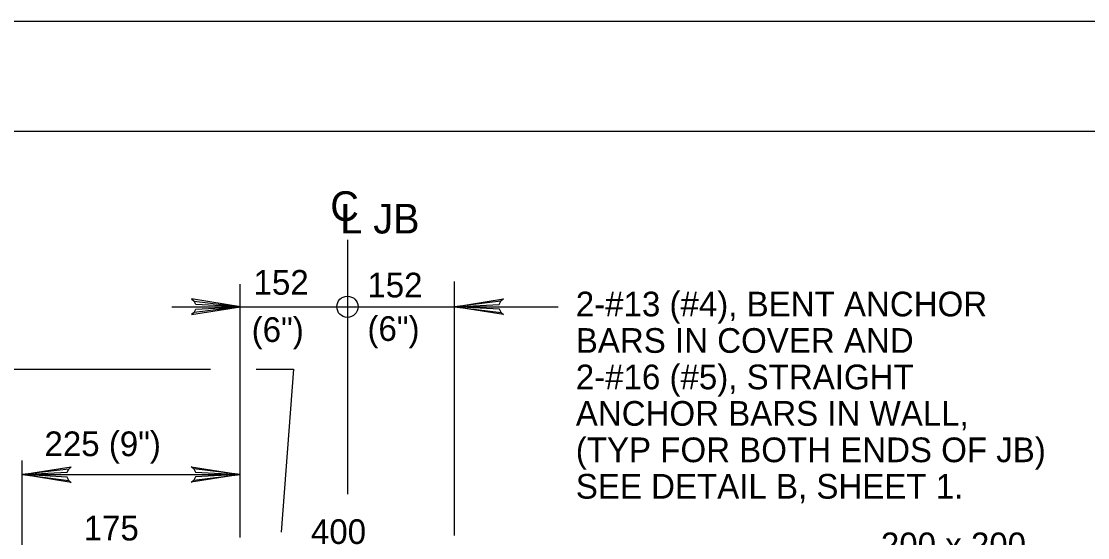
# Model space of a CAD drawing. Extents: x 638455 to 640199, y 298558 to 299152.
# Drawn here: x 639455 to 639600, y 299082 to 299152.2 of the extents above; entities that cross this region are included whole.
import ezdxf

# ---------------------------------------------------------------- set-up
doc = ezdxf.new("R2010")
doc.units = 0
for name, color, linetype in [('1', 7, 'Continuous'), ('2', 7, 'Continuous'), ('3', 7, 'Continuous'), ('PLT-BNDY', 7, 'Continuous')]:
    doc.layers.add(name, color=color, linetype=linetype)

msp = doc.modelspace()

# ---------------------------------------------------------------- linework, layer by layer
at = {"layer": '1'}
msp.add_lwpolyline([(640119.61, 298573.25), (640119.61, 299137.25), (639333.61, 299137.25), (639333.61, 298573.25), (640119.61, 298573.25), (640119.61, 298599.61), (639919.61, 298599.61), (639919.61, 298664.29), (640119.61, 298664.29), (640119.61, 298693.25), (639919.61, 298693.25), (639919.61, 298573.25), (639998.42, 298573.25), (639998.42, 298599.61), (639998.42, 298573.25), (640075.42, 298573.25), (640075.42, 298599.61), (640075.42, 298587.29), (640119.61, 298587.29)], dxfattribs=at)
msp.add_circle((639499.32, 299113.41), 1.44, dxfattribs=at)
at = {"layer": '2'}
for p, q in [((639499.32, 299122.53), (639499.32, 299107.89)), ((639484.75, 299082.03), (639484.75, 299116.5)), ((639513.88, 299082.27), (639513.88, 299116.84)), ((639475.44, 299113.41), (639484.75, 299113.41)), ((639484.75, 299113.41), (639499.32, 299113.41)), ((639499.32, 299113.41), (639513.88, 299113.41)), ((639513.88, 299113.41), (639527.95, 299113.41)), ((639499.32, 299111.34), (639499.32, 299087.9)), ((639437.62, 299104.91), (639480.7, 299104.91)), ((639486.91, 299104.91), (639491.97, 299104.91)), ((639491.97, 299104.91), (639490.29, 299082.72)), ((639455.11, 299069.07), (639455.11, 299092.49)), ((639455.11, 299090.57), (639484.75, 299090.57))]:
    msp.add_line(p, q, dxfattribs=at)
for points in [[(639478.46, 299112.62), (639478.7, 299113.07), (639484.8, 299113.41), (639478.46, 299112.62), (639478.14, 299112.34), (639484.8, 299113.41), (639478.71, 299113.71), (639478.49, 299114.17), (639484.8, 299113.41), (639478.14, 299114.47), (639478.49, 299114.17)], [(639520.21, 299112.62), (639519.98, 299113.07), (639513.88, 299113.41), (639520.21, 299112.62), (639520.54, 299112.34), (639513.88, 299113.41), (639519.97, 299113.71), (639520.19, 299114.17), (639513.88, 299113.41), (639520.54, 299114.47), (639520.19, 299114.17)], [(639461.45, 299089.78), (639461.21, 299090.24), (639455.11, 299090.57), (639461.45, 299089.78), (639461.77, 299089.5), (639455.11, 299090.57), (639461.2, 299090.88), (639461.42, 299091.33), (639455.11, 299090.57), (639461.77, 299091.63), (639461.42, 299091.33)], [(639478.42, 299091.37), (639478.66, 299090.91), (639484.75, 299090.57), (639478.42, 299091.37), (639478.09, 299091.65), (639484.75, 299090.57), (639478.66, 299090.27), (639478.44, 299089.82), (639484.75, 299090.57), (639478.09, 299089.52), (639478.44, 299089.82)]]:
    msp.add_lwpolyline(points, dxfattribs=at)
at = {"layer": 'PLT-BNDY'}
msp.add_lwpolyline([(639295.61, 299152.25), (640136.61, 299152.25), (640136.61, 298558.25), (639295.61, 298558.25)], close=True, dxfattribs=at)

# ---------------------------------------------------------------- texts
at = {"layer": '1'}
for p in [(639486.3, 299108.62), (639502.04, 299108.76)]:
    msp.add_text('(6")', height=3.36, dxfattribs=at).set_placement(p)
at = {"layer": '3'}
for s, height, p in [('C', 4.03, (639496.99, 299125.09)), ('L JB', 4.032, (639498.34, 299123.38)), ('152', 3.36, (639486.56, 299115.05)), ('152', 3.36, (639502.03, 299114.68)), ('2-#13 (#4), BENT ANCHOR', 3.36, (639530.37, 299112.1)), ('BARS IN COVER AND', 3.36, (639530.37, 299107.14)), ('2-#16 (#5), STRAIGHT', 3.36, (639530.37, 299102.18)), ('ANCHOR BARS IN WALL,', 3.36, (639530.37, 299097.22)), ('225 (9")', 3.36, (639458.13, 299093.08)), ('(TYP FOR BOTH ENDS OF JB)', 3.36, (639530.37, 299092.26)), ('SEE DETAIL B, SHEET 1.', 3.36, (639530.37, 299087.3)), ('175', 3.36, (639463.46, 299081.61)), ('400', 3.36, (639494.36, 299081.13)), ('200 x 200', 3.36, (639571.85, 299079.33))]:
    msp.add_text(s, height=height, dxfattribs=at).set_placement(p)

doc.saveas('drawing.dxf')
